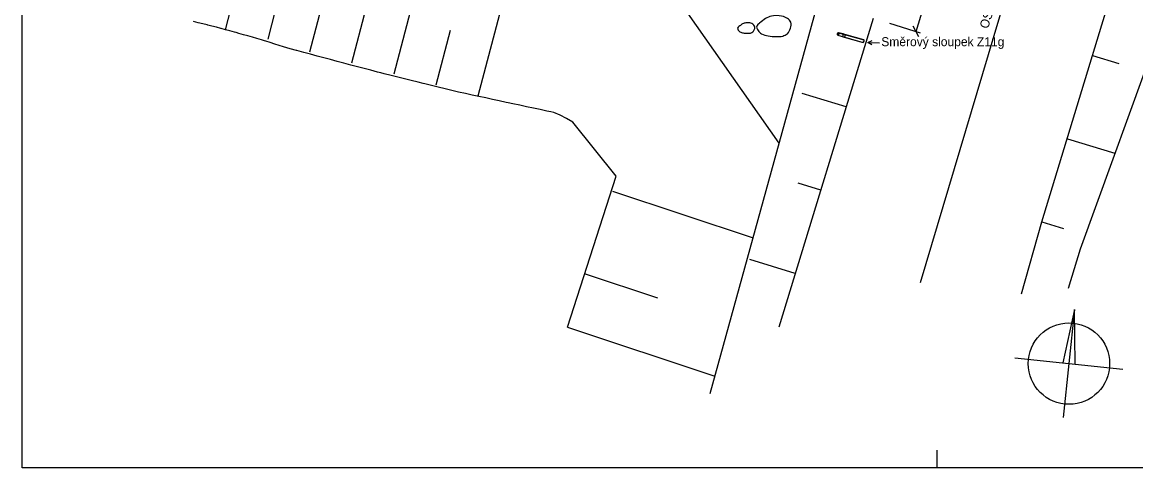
# Model space of a CAD drawing. Extents: x -577013.5 to -576971.5, y -1164310.3 to -1164280.6.
# Drawn here: x -577013.45 to -576987.9, y -1164310.26 to -1164300.03 of the extents above; entities that cross this region are included whole.
import ezdxf

# ---------------------------------------------------------------- set-up
doc = ezdxf.new("R2010")
doc.units = 0
for name, color, linetype in [('21', 7, 'Continuous'), ('37', 7, 'Continuous'), ('60', 7, 'Continuous'), ('61', 7, 'Continuous'), ('Ram PR2a', 7, 'Continuous'), ('Rámy', 7, 'Continuous'), ('Směrové sloupky detail', 7, 'Continuous'), ('V_N1_detaily', 7, 'Continuous'), ('Vrstva 1', 7, 'Continuous'), ('Šrafy', 7, 'Continuous')]:
    doc.layers.add(name, color=color, linetype=linetype)

msp = doc.modelspace()

# ---------------------------------------------------------------- linework, layer by layer
for p, q in [((-576992.94, -1164300.242), (-576989.668, -1164289.602)), ((-576996.082, -1164302.805), (-576998.818, -1164298.9)), ((-577009.416, -1164300.041), (-577009.521, -1164300.015)), ((-577009.312, -1164300.066), (-577009.416, -1164300.041)), ((-577009.207, -1164300.093), (-577009.312, -1164300.066)), ((-577009.193, -1164300.096), (-577009.207, -1164300.093)), ((-577009.103, -1164300.119), (-577009.193, -1164300.096)), ((-577008.999, -1164300.146), (-577009.103, -1164300.119)), ((-576993.548, -1164300.055), (-576992.845, -1164300.271)), ((-576992.874, -1164300.367), (-576993.007, -1164300.117)), ((-577008.895, -1164300.174), (-577008.999, -1164300.146)), ((-577008.889, -1164300.175), (-577008.895, -1164300.174)), ((-577008.791, -1164300.201), (-577008.889, -1164300.175)), ((-577008.687, -1164300.229), (-577008.791, -1164300.201)), ((-577008.584, -1164300.258), (-577008.687, -1164300.229)), ((-577008.542, -1164300.269), (-577008.584, -1164300.258)), ((-577008.48, -1164300.287), (-577008.542, -1164300.269)), ((-577008.377, -1164300.316), (-577008.48, -1164300.287)), ((-577008.274, -1164300.345), (-577008.377, -1164300.316)), ((-577008.172, -1164300.375), (-577008.274, -1164300.345)), ((-577008.069, -1164300.406), (-577008.172, -1164300.375)), ((-577007.966, -1164300.436), (-577008.069, -1164300.406)), ((-577007.898, -1164300.457), (-577007.966, -1164300.436)), ((-577007.864, -1164300.467), (-577007.898, -1164300.457)), ((-577007.762, -1164300.499), (-577007.864, -1164300.467)), ((-577007.66, -1164300.53), (-577007.762, -1164300.499)), ((-577007.558, -1164300.563), (-577007.66, -1164300.53)), ((-577007.457, -1164300.595), (-577007.558, -1164300.563)), ((-577007.303, -1164300.638), (-577007.457, -1164300.595)), ((-577007.158, -1164300.678), (-577007.303, -1164300.638)), ((-577007.149, -1164300.68), (-577007.158, -1164300.678)), ((-577006.995, -1164300.722), (-577007.149, -1164300.68)), ((-577006.841, -1164300.764), (-577006.995, -1164300.722)), ((-577006.687, -1164300.806), (-577006.841, -1164300.764)), ((-577006.533, -1164300.848), (-577006.687, -1164300.806)), ((-577006.379, -1164300.889), (-577006.533, -1164300.848)), ((-577006.225, -1164300.93), (-577006.379, -1164300.889)), ((-577006.193, -1164300.939), (-577006.225, -1164300.93)), ((-577006.07, -1164300.971), (-577006.193, -1164300.939)), ((-577005.916, -1164301.012), (-577006.07, -1164300.971)), ((-577005.762, -1164301.053), (-577005.916, -1164301.012)), ((-577005.608, -1164301.093), (-577005.762, -1164301.053)), ((-577005.453, -1164301.133), (-577005.608, -1164301.093)), ((-577005.299, -1164301.173), (-577005.453, -1164301.133)), ((-577005.225, -1164301.192), (-577005.299, -1164301.173)), ((-577005.144, -1164301.213), (-577005.225, -1164301.192)), ((-577004.99, -1164301.252), (-577005.144, -1164301.213)), ((-577004.835, -1164301.292), (-577004.99, -1164301.252)), ((-577004.68, -1164301.331), (-577004.835, -1164301.292)), ((-577004.526, -1164301.37), (-577004.68, -1164301.331)), ((-577004.371, -1164301.408), (-577004.526, -1164301.37)), ((-577004.256, -1164301.437), (-577004.371, -1164301.408)), ((-577004.216, -1164301.447), (-577004.256, -1164301.437)), ((-577004.061, -1164301.485), (-577004.216, -1164301.447)), ((-577003.906, -1164301.523), (-577004.061, -1164301.485)), ((-577003.751, -1164301.561), (-577003.906, -1164301.523)), ((-577003.596, -1164301.597), (-577003.751, -1164301.561)), ((-577003.44, -1164301.632), (-577003.596, -1164301.597)), ((-577003.284, -1164301.666), (-577003.44, -1164301.632)), ((-577003.128, -1164301.701), (-577003.284, -1164301.666)), ((-577002.972, -1164301.735), (-577003.128, -1164301.701)), ((-577002.817, -1164301.769), (-577002.972, -1164301.735)), ((-577002.661, -1164301.803), (-577002.817, -1164301.769)), ((-577002.505, -1164301.837), (-577002.661, -1164301.803)), ((-577002.349, -1164301.871), (-577002.505, -1164301.837)), ((-577002.305, -1164301.88), (-577002.349, -1164301.871)), ((-577002.192, -1164301.904), (-577002.305, -1164301.88)), ((-577002.036, -1164301.937), (-577002.192, -1164301.904)), ((-577001.88, -1164301.97), (-577002.036, -1164301.937)), ((-577001.724, -1164302.003), (-577001.88, -1164301.97)), ((-577001.567, -1164302.035), (-577001.724, -1164302.003)), ((-577001.411, -1164302.068), (-577001.567, -1164302.035)), ((-577001.326, -1164302.085), (-577001.411, -1164302.068)), ((-577001.255, -1164302.1), (-577001.326, -1164302.085)), ((-577001.107, -1164302.166), (-577001.255, -1164302.1)), ((-577000.96, -1164302.238), (-577001.107, -1164302.166)), ((-577000.818, -1164302.326), (-577000.96, -1164302.238)), ((-576999.821, -1164303.567), (-577000.818, -1164302.326))]:
    msp.add_line(p, q)
at = {"layer": '21'}
msp.add_line((-577000.943, -1164307.026), (-576999.821, -1164303.567), dxfattribs=at)
at = {"layer": '37'}
for p, q in [((-576990.056, -1164304.615), (-576986.686, -1164293.545)), ((-576993.922, -1164299.942), (-576996.088, -1164307.026)), ((-576990.523, -1164306.268), (-576990.056, -1164304.615))]:
    msp.add_line(p, q, dxfattribs=at)
at = {"layer": '60'}
for p, q in [((-576989.166, -1164305.235), (-576985.286, -1164294.515)), ((-576994.958, -1164298.727), (-576997.672, -1164308.563)), ((-576989.441, -1164306.138), (-576989.166, -1164305.235))]:
    msp.add_line(p, q, dxfattribs=at)
at = {"layer": '61'}
for p, q in [((-576988.886, -1164300.795), (-576988.286, -1164300.975)), ((-576994.546, -1164301.975), (-576995.556, -1164301.665)), ((-576989.466, -1164302.705), (-576988.376, -1164303.035)), ((-576999.906, -1164303.905), (-576996.682, -1164304.98)), ((-576995.126, -1164303.885), (-576995.646, -1164303.725)), ((-576990.056, -1164304.615), (-576989.556, -1164304.765)), ((-576995.716, -1164305.795), (-576996.756, -1164305.475)), ((-577000.536, -1164305.805), (-576998.876, -1164306.355)), ((-577000.943, -1164307.026), (-576997.559, -1164308.154))]:
    msp.add_line(p, q, dxfattribs=at)
at = {"layer": 'Ram PR2a'}
for p, q in [((-576989.3, -1164306.627), (-576989.572, -1164307.851)), ((-576989.3, -1164306.627), (-576989.56, -1164309.105)), ((-576990.669, -1164307.736), (-576988.191, -1164307.996))]:
    msp.add_line(p, q, dxfattribs=at)
msp.add_lwpolyline([(-576989.3, -1164306.627), (-576989.43, -1164307.866), (-576989.287, -1164307.881)], close=True, dxfattribs=at)
msp.add_circle((-576989.43, -1164307.866), 0.934, dxfattribs=at)
at = {"layer": 'Rámy'}
for p, q in [((-577013.454, -1164310.256), (-577013.454, -1164280.556)), ((-576992.454, -1164310.256), (-576992.454, -1164309.856)), ((-576971.454, -1164310.256), (-577013.454, -1164310.256))]:
    msp.add_line(p, q, dxfattribs=at)
at = {"layer": 'Směrové sloupky detail'}
for p, q in [((-576994.734, -1164300.328), (-576994.157, -1164300.492)), ((-576994.717, -1164300.27), (-576994.14, -1164300.434))]:
    msp.add_line(p, q, dxfattribs=at)
for points in [[(-576994.734, -1164300.328), (-576994.633, -1164300.357), (-576994.633, -1164300.357)], [(-576994.734, -1164300.328), (-576994.734, -1164300.328)], [(-576994.616, -1164300.299), (-576994.717, -1164300.27)], [(-576994.717, -1164300.27), (-576994.717, -1164300.27)], [(-576994.633, -1164300.357), (-576994.589, -1164300.369)], [(-576994.573, -1164300.311), (-576994.573, -1164300.311), (-576994.616, -1164300.299)], [(-576994.589, -1164300.369), (-576994.157, -1164300.492)], [(-576994.14, -1164300.434), (-576994.573, -1164300.311)]]:
    msp.add_lwpolyline(points, dxfattribs=at)
for centre, start_param, end_param in [((-576994.726, -1164300.299), 0, 3.141593), ((-576994.726, -1164300.299), 3.141603, 6.283175), ((-576994.726, -1164300.299), 3.141603, 6.283175), ((-576994.625, -1164300.328), 3.141603, 6.283185), ((-576994.625, -1164300.328), 3.141603, 6.283175), ((-576994.581, -1164300.34), 3.141603, 6.283175), ((-576994.581, -1164300.34), 3.141593, 6.283175), ((-576994.148, -1164300.463), 3.141593, 6.283185)]:
    msp.add_ellipse(centre, major_axis=(0.0082, 0.0289), ratio=0.5, start_param=start_param, end_param=end_param, dxfattribs=at)
msp.add_ellipse((-576994.726, -1164300.299), major_axis=(0.0082, 0.0289), ratio=0.5, dxfattribs=at)
at = {"layer": 'V_N1_detaily'}
for points in [[(-576995.891, -1164300.294), (-576996.001, -1164300.348), (-576996.151, -1164300.359), (-576996.331, -1164300.344), (-576996.486, -1164300.296), (-576996.564, -1164300.218), (-576996.597, -1164300.122), (-576996.531, -1164300.054), (-576996.395, -1164299.943), (-576996.257, -1164299.891), (-576996.079, -1164299.88), (-576995.891, -1164299.943), (-576995.817, -1164300.031), (-576995.819, -1164300.169), (-576995.891, -1164300.294)], [(-576996.684, -1164300.251), (-576996.739, -1164300.278), (-576996.814, -1164300.283), (-576996.904, -1164300.276), (-576996.981, -1164300.252), (-576997.02, -1164300.213), (-576997.037, -1164300.165), (-576997.004, -1164300.131), (-576996.936, -1164300.075), (-576996.867, -1164300.049), (-576996.778, -1164300.044), (-576996.684, -1164300.075), (-576996.647, -1164300.119), (-576996.648, -1164300.188), (-576996.684, -1164300.251)]]:
    msp.add_spline(points, degree=3, dxfattribs=at)
at = {"layer": 'Vrstva 1'}
for p, q in [((-576992.834, -1164306.008), (-576986.608, -1164285.099)), ((-576994.05, -1164300.492), (-576993.775, -1164300.505))]:
    msp.add_line(p, q, dxfattribs=at)
msp.add_lwpolyline([(-576993.953, -1164300.547), (-576994.05, -1164300.492), (-576993.948, -1164300.447)], dxfattribs=at)
at = {"layer": 'Šrafy'}
for p, q in [((-577008.791, -1164300.201), (-577007.871, -1164296.692)), ((-577006.856, -1164300.708), (-577005.921, -1164297.14)), ((-577004.922, -1164301.216), (-577003.979, -1164297.621)), ((-577002.987, -1164301.723), (-577002.038, -1164298.102)), ((-577007.814, -1164300.419), (-577007.489, -1164299.18)), ((-577005.889, -1164300.962), (-577005.559, -1164299.705)), ((-577003.954, -1164301.469), (-577003.625, -1164300.212))]:
    msp.add_line(p, q, dxfattribs=at)

# ---------------------------------------------------------------- texts
at = {"layer": 'Vrstva 1'}
msp.add_text('OSA SILNICE III/4161', height=0.20663, rotation=72.4419, dxfattribs=at).set_placement((-576991.29, -1164300.194))
msp.add_text('Směrový sloupek Z11g', height=0.20663, dxfattribs=at).set_placement((-576993.738, -1164300.58))

doc.saveas('drawing.dxf')
